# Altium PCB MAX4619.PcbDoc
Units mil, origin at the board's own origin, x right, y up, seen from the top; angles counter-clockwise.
Board outline 2750 x 2500 mil, 2 copper layers (Top, Bottom), stack 62 mil thick; 43 components, 17 nets, 117 pads, 7 vias.
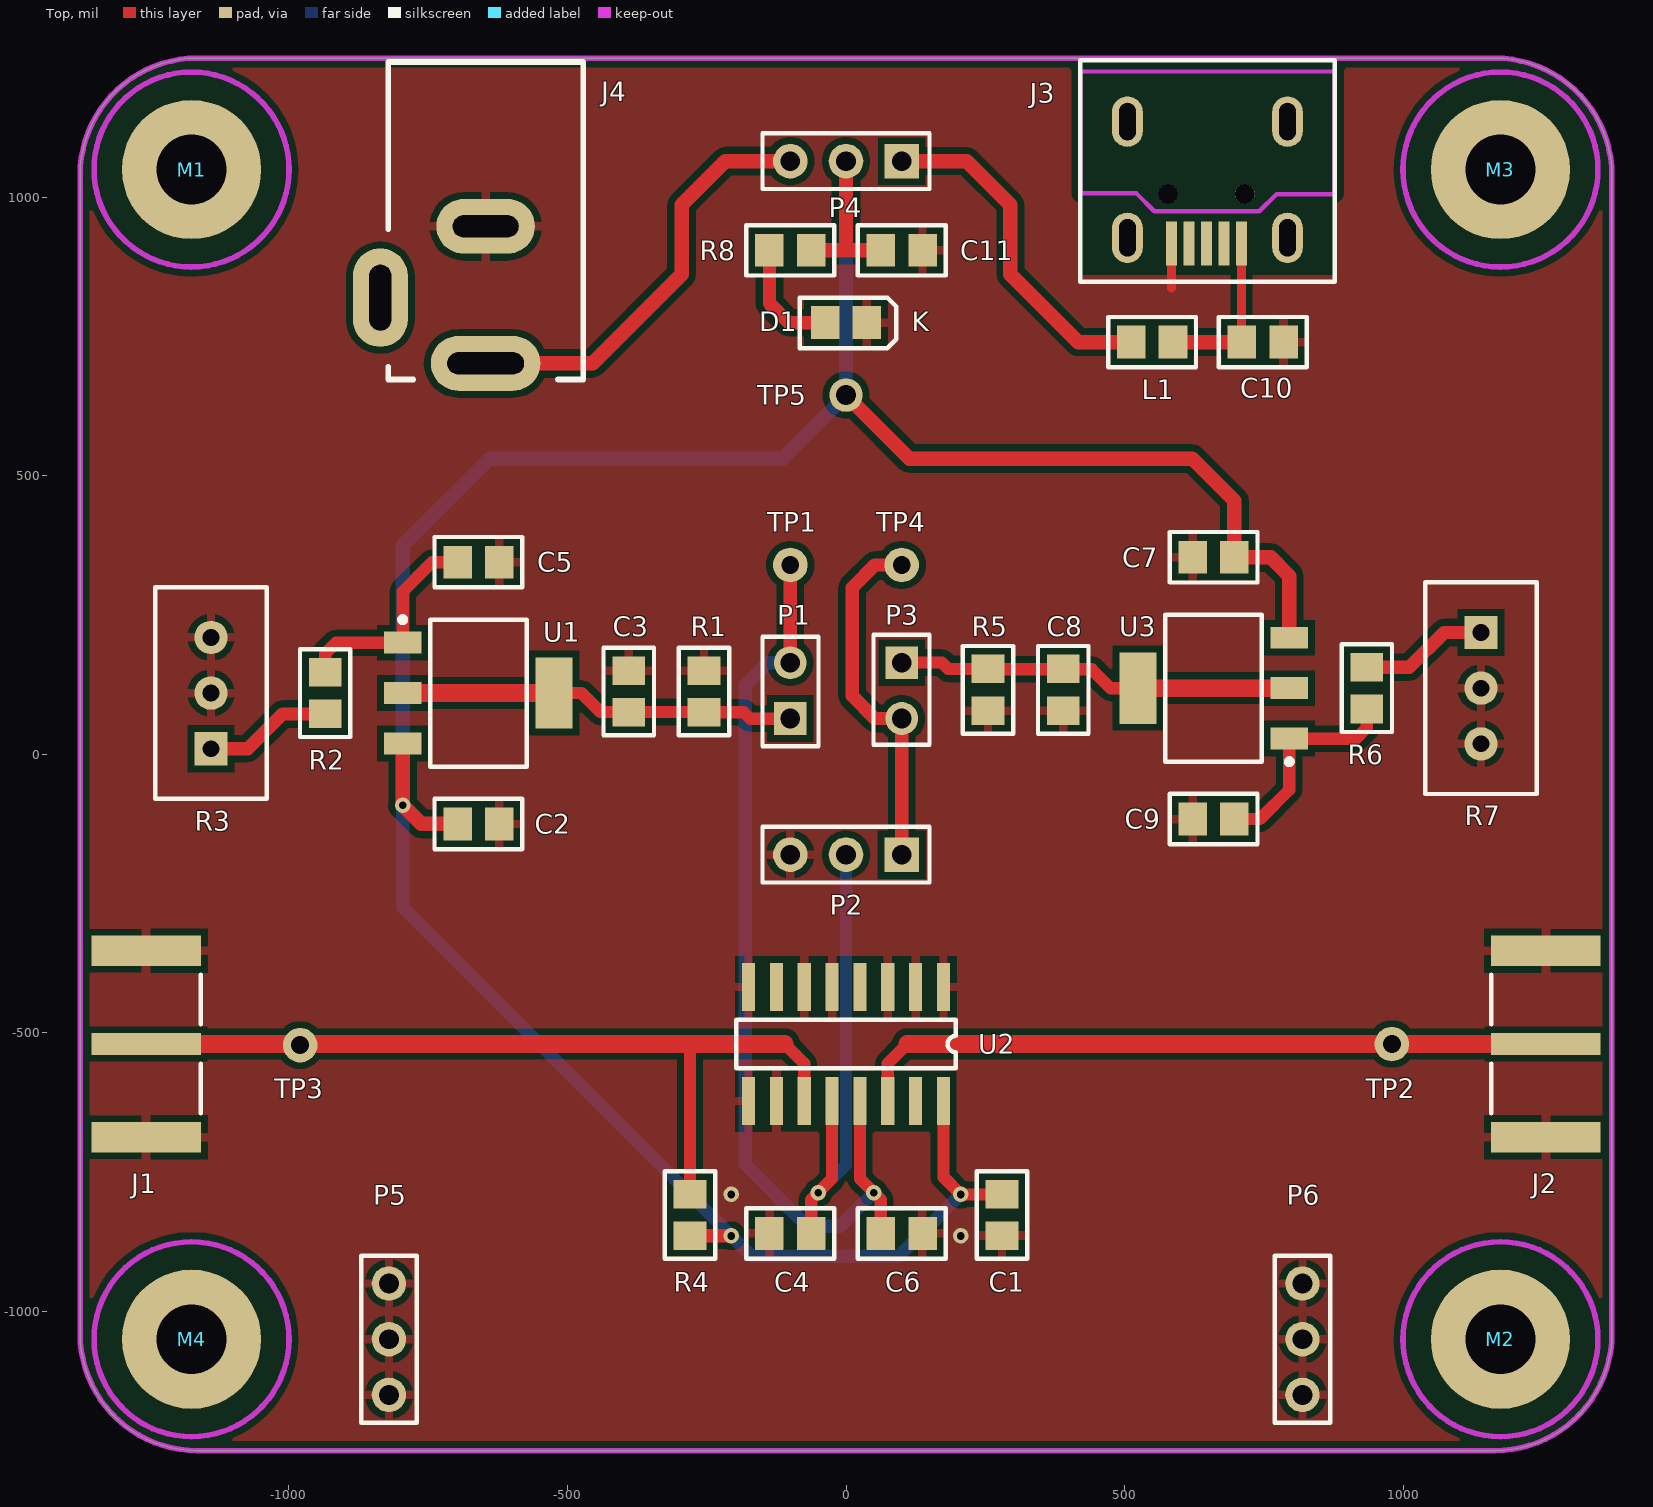
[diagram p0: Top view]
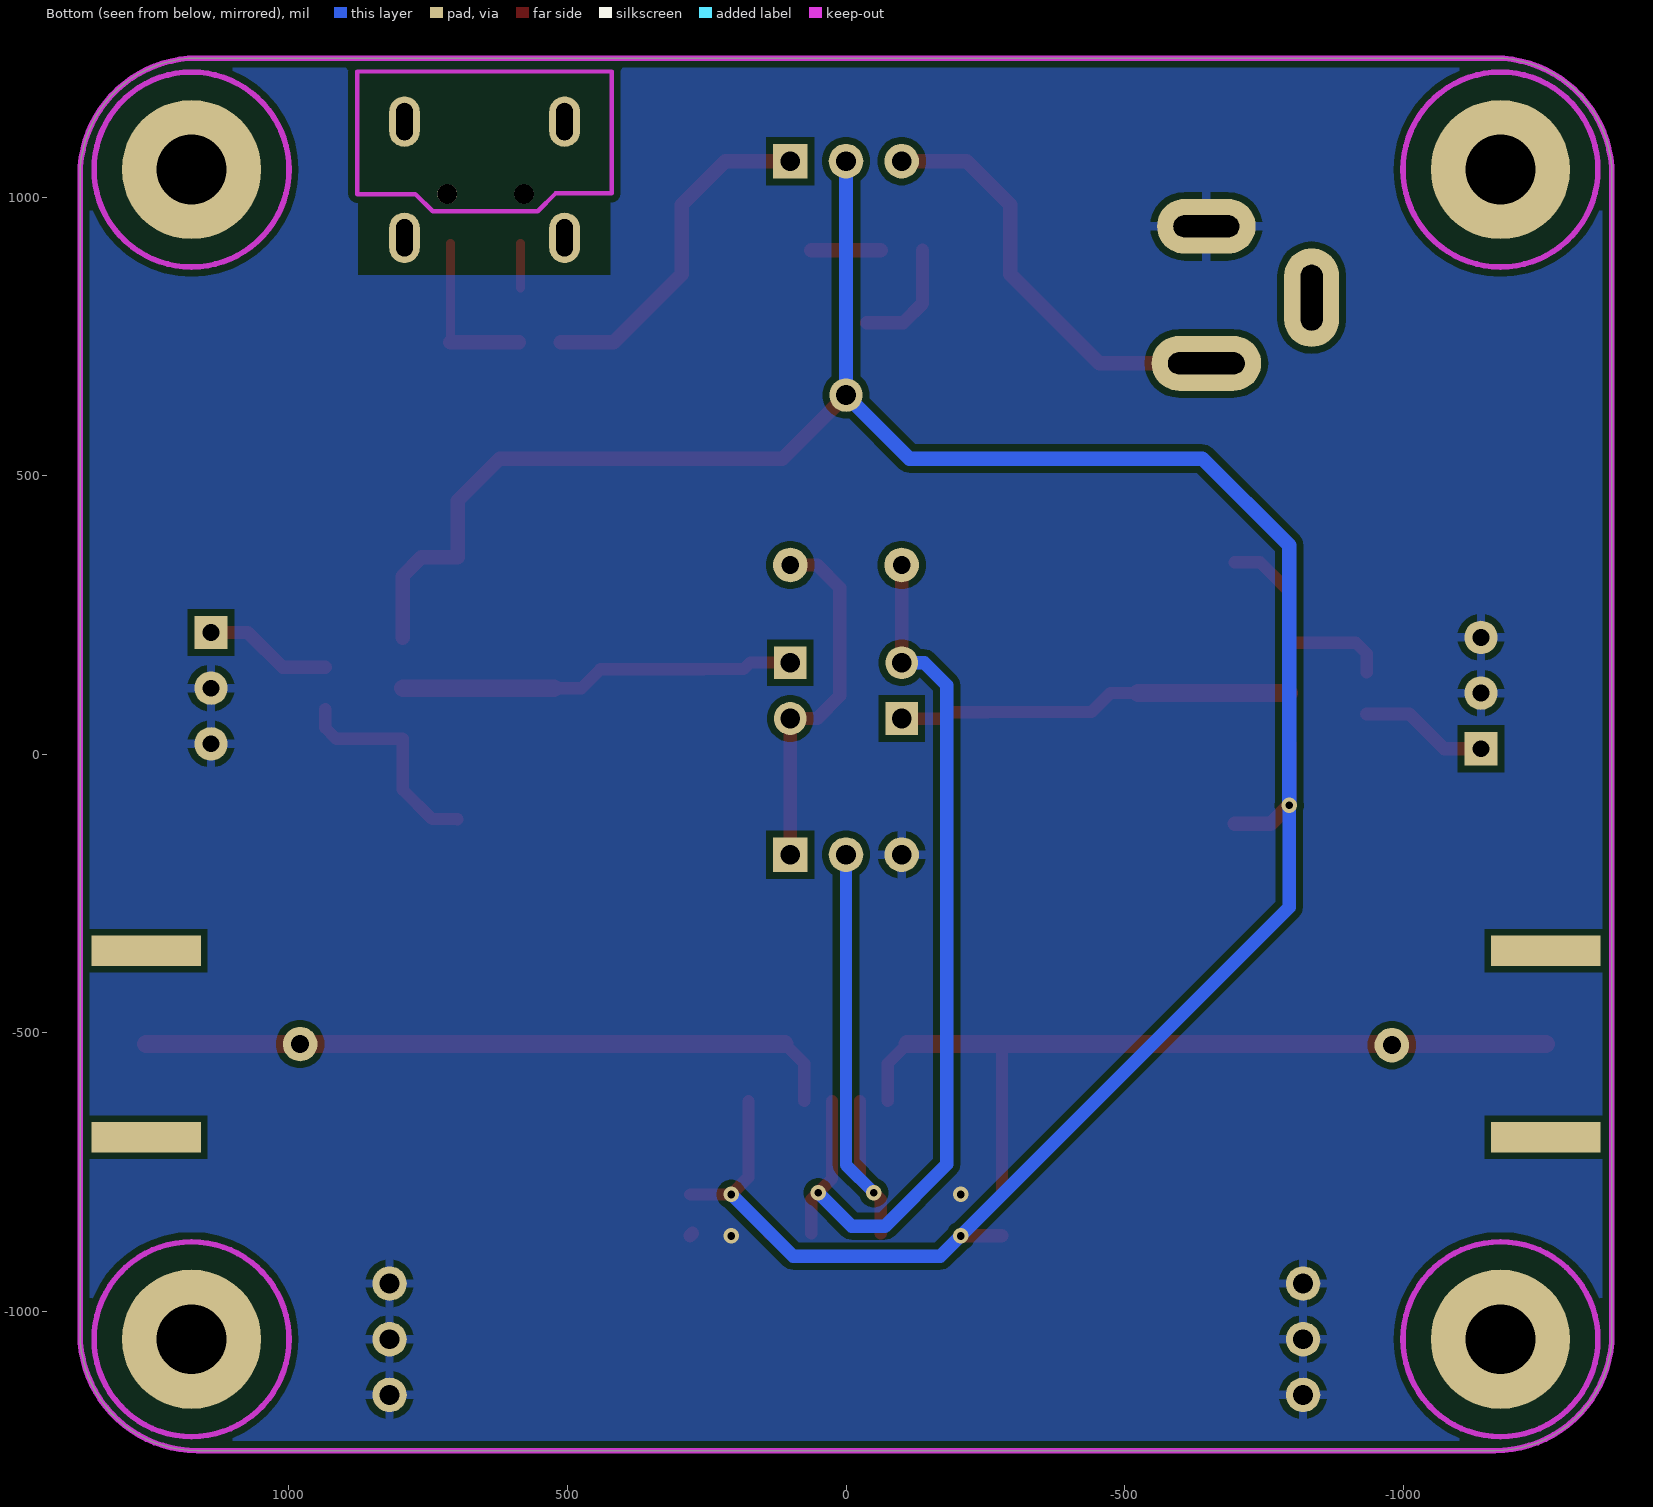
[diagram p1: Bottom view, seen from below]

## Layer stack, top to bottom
Top Solder: solder mask 0.4, Solder Resist, Dk 3.5
Top: signal copper 1.4
Dielectric1: core 59.2, FR-4, Dk 4.8
Bottom: signal copper 1.4
Bottom Solder: solder mask 0.4, Solder Resist, Dk 3.5

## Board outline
-1375,-1040 -1375,1040 cw(c-1165,1040) -1165,1250 1165,1250 cw(c1165,1040) 1375,1040 1375,-1040 cw(c1165,-1040) 1165,-1250 -1165,-1250 cw(c-1165,-1040)

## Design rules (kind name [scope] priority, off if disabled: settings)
Clearance Clearance_1 [InPolygon] p1: gap=12 ignorepadtopadclearanceinfootprint=FALSE except(0: Arc-Hole Track-Hole SMDPad-Hole THPad-Hole Via-Hole Fill-Hole Poly-Hole Region-Hole Text-Hole)
Clearance [All] p2: gap=9 ignorepadtopadclearanceinfootprint=FALSE except(0: Arc-Hole Track-Hole SMDPad-Hole THPad-Hole Via-Hole Fill-Hole Poly-Hole Region-Hole Text-Hole)
ComponentClearance [All] p1 off: gap=0 collisioncheckmode=3 verticalgap=10 showdistances=FALSE
FabricationTestPointUsage TestPointUsage [All] p1: valid=0 allowmultiple=FALSE
FabricationTestpoint Testpoint [All] p1: side=3 testpointundercomponent=TRUE minsize=40 maxsize=100 preferedsize=60 minholesize=0 maxholesize=40 preferedholesize=32 testpointgrid=1 allowsidetop=TRUE allowsidebottom=TRUE usegrid=TRUE gridtolerance=0.01
HoleSize [All] p1: absolutevalues=TRUE maxlimit=250 minlimit=10 maxpercent=80.000 minpercent=20.000
MinimumAnnularRing [All] p1: minimumring=7
PlaneClearance [All] p1: clearance=12
PlaneConnect [All] p1: planeconnectstyle=Relief reliefexpansion=12 reliefentries=4 reliefconductorwidth=12 reliefairgap=12
PolygonConnect [IsVia] p1: connectstyle=Direct reliefconductorwidth=10 reliefentries=4 polygonreliefangle="90 Angle" airgapwidth=10
PolygonConnect PolygonConnect_1 [All] p2: connectstyle=Relief reliefconductorwidth=16 reliefentries=4 polygonreliefangle="90 Angle" airgapwidth=12
RoutingVias [All] p1: holewidth=14 width=28 viastyle="Through Hole" minholewidth=14 minwidth=28 maxholewidth=14 maxwidth=28
SilkToSolderMaskClearance SilkscreenOverComponentPads [IsPad] p1: minsilkscreentomaskgap=10 clearancetoexposedcopper=TRUE
SolderMaskExpansion SolderMaskExpansion_1 [(IsVia)] p1: expansion=-14 istentingtop=FALSE
SolderMaskExpansion [All] p2: expansion=4 istentingtop=FALSE
Width [All] p1: maxlimit=32 minlimit=10 preferedwidth=12
23 further rules are at their usual default settings.

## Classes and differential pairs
component class MAX4619: C1 C2 C3 C4 C5 C6 C7 C8 C9 C10 C11 D1 J1 J2 J3 J4 L1 P1 P2 P3 P4 P5 P6 R1 R2 R3 R4 R5 R6 R7 R8 TP1 TP2 TP3 TP4 TP5 U1 U2 U3

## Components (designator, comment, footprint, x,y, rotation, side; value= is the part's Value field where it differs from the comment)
C1 "Cap" CC2012-0805 280,-827 r90 top value=0.1uF
C2 "Cap" CC2012-0805 -660,-125 r180 top value=1uF
C3 "Cap" CC2012-0805 -390,112.95 r270 top value=2.2uF
C4 "Cap" CC2012-0805 -100,-860 r0 top value=0.1uF
C5 "Cap" CC2012-0805 -660,345 r180 top value=0.1uF
C6 "Cap" CC2012-0805 100,-860 r180 top value=0.1uF
C7 "Cap" CC2012-0805 660,353.86 r0 top value=1uF
C8 "Cap" CC2012-0805 390,115.91 r90 top value=2.2uF
C9 "Cap" CC2012-0805 660,-116.14 r0 top value=0.1uF
C10 "Cap" CC2012-0805 748.27,740 r180 top value=0.01uF
C11 "Cap" CC2012-0805 100,905 r180 top value=0.1uF
D1 "LED" "CC2012-0805 LED" 0,775 r0 top
J1 "32K145-400L5" ROS-32K145-400L5_V -1355,-520 r90 top locked
J2 "32K145-400L5" ROS-32K145-400L5_V 1355,-520 r270 top locked
J3 "UX60-MB-5S8" "HRS UX60-MB-5S8 MINI-USB" 505.27,1136 r270 top locked
J4 "PJ-202A" PJ-202A-SLOTS -647,948 r180 top
L1 "Inductor" CC2012-0805 549.67,740 r180 top value=220R@100MHz
M1 "Comment" MOUNTING-HOLE-4-40 -1175,1050 r0 top locked
M2 "Comment" MOUNTING-HOLE-4-40 1175,-1050 r0 top locked
M3 "Comment" MOUNTING-HOLE-4-40 1175,1050 r0 top locked
M4 "Comment" MOUNTING-HOLE-4-40 -1175,-1050 r0 top locked
P1 "Header 2" HEADER2 -100,64.43 r0 top
P2 "Header 3" HEADER3#1 100,-180 r180 top
P3 "Header 2" HEADER2 100,164.43 r180 top
P4 "Header 3" HEADER3#1 100,1065 r180 top
P5 "Header 3" HEADER3#2 -820.5,-950 r270 top
P6 "Header 3" HEADER3#2 819.5,-950 r270 top
R1 "Res1" CC2012-0805 -255,112.95 r90 top value=DNP
R2 "Res1" CC2012-0805 -935,110 r270 top value="0 ohm"
R3 "500k" BOURNS-3296 -1140,110 r90 top
R4 "Res1" CC2012-0805 -280,-827 r90 top value=10k
R5 "Res1" CC2012-0805 255,115.91 r270 top value=DNP
R6 "Res1" CC2012-0805 935,118.86 r90 top value="0 ohm"
R7 "500k" BOURNS-3296 1140,118.86 r270 top
R8 "Res1" CC2012-0805 -100,905 r180 top value=10k
TP1 "TESTPOINT" TESTPOINT#1 -110,380 r90 top
TP2 "TESTPOINT" TESTPOINT#2 980,-520 r90 top
TP3 "TESTPOINT" TESTPOINT#2 -980,-522 r90 top
TP4 "TESTPOINT" TESTPOINT#3 110,-151.14 r270 top
TP5 "TESTPOINT" TESTPOINT#4 0,645 r90 top
U1 "LT3082IST#TRPBF" LT-ST-3-SOT-223_M -660,110 r0 top
U2 "MAX4619CSE+" SO-G16 0,-520 r180 top locked
U3 "LT3082IST#TRPBF" LT-ST-3-SOT-223_M 660,118.86 r180 top

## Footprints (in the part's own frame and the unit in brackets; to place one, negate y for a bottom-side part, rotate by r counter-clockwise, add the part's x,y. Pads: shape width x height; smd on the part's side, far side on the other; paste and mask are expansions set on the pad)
BOURNS-3296 [mil]
  rect 60x60 hole 30: CCW(-100,0)
  round 60 hole 30: CW(100,0) W(0,0)
  silkscreen extent -190,-100 190,100
CC2012-0805 [mm]
  rect 1.3x1.5 smd: 1(-0.95,0) 2(0.95,0)
  silkscreen extent -2,-1.15 2,1.15
"CC2012-0805 LED" [mm]
  rect 1.3x1.5 smd: 1(-0.95,0) 2(0.95,0)
  silkscreen extent -2.12,-1.16 2.3,1.14
HEADER2 [mm]
  rect 1.5x1.5 hole 0.9: 1(0,0)
  round 1.5 hole 0.9: 2(0,2.54)
  silkscreen extent -1.27,-1.27 1.29,3.73
HEADER3#1 [mil]
  rect 62x62 hole 35.43: 1(0,0)
  round 62 hole 35.43: 2(100,0) 3(200,0)
  silkscreen extent -50,-50 250,50
HEADER3#2 [mil]
  round 62 hole 35.43: 1(0,0) 2(100,0) 3(200,0)
  silkscreen extent -50,-50 250,50
"HRS UX60-MB-5S8 MINI-USB" [mm]
  oval 2.3x1.4 hole 0.762 slot 1.7 at 0 deg: 0(0,7.3) 0(0,0) 0(5.3,7.3) 0(5.3,0)
  round 0.9 hole 0.9 unplated: 0(3.3,5.35) 0(3.3,1.85)
  rect 2x0.5 smd: 1(5.55,5.2) 2(5.55,4.4) 3(5.55,3.6) 4(5.55,2.8) 5(5.55,2)
  Keep-Out Layer lines w0.203: 3.277,-2.145 -2.286,-2.145 -2.286,9.462 3.302,9.462 3.302,6.804 4.089,6.017 4.089,5.348 4.089,1.842 4.089,1.226 3.277,0.413 3.277,-2.145
  silkscreen extent -2.8,-2.15 7.3,9.45
LT-ST-3-SOT-223_M [mm] "SOT223, 4-Leads, Body 6.505x3.505mm, Pitch 2.3mm, IPC Low Density"
  rect 1.7x1 smd: 1(-3.45,2.3) 2(-3.45,0) 3(-3.45,-2.3)
  rect 1.7x3.25 smd: 4(3.45,0)
  silkscreen extent -3.57,-3.35 2.2,3.47, body extent -1.86,-3.35 1.86,3.35, height 1.8
MOUNTING-HOLE-4-40 [mil] "Mounting Hole w/ Annular Ring US #4-40/Metric M3"
  round 250 hole 125: 0(0,0)
  Keep-Out Layer circle w10: c0,0 r175
PJ-202A-SLOTS [mm]
  oval 5x2.5 hole 1 slot 3.5 at 0 deg mask+0.075: 1(0,6.248)
  oval 4.5x2.5 hole 1 slot 3 at 0 deg mask+0.075: 2(0,0)
  oval 2.5x4.5 hole 1 slot 3 at 90 deg mask+0.075: 3(4.801,3.251)
  silkscreen extent -4.45,-7.49 4.45,6.98
ROS-32K145-400L5_V [mm] "SMA Right Angle Jack, Edge Mount, 14.25x9.5x4.46mm, Rosenberger Recommended"
  rect 1x5 smd: 1(0,-2.5)
  rect 1.4x5 smd: MP(-4.25,-2.5) MP(4.25,-2.5)
  rect 1.4x5 smd far side paste-2: ""(-4.25,-2.5) ""(4.25,-2.5)
  silkscreen extent -3.15,-5 3.15,-5, body extent -4.75,-4.75 4.75,9.5, height 4.46
SO-G16 [mm]
  rect 0.6x2.2 smd: 1(-4.445,-2.6) 2(-3.175,-2.6) 3(-1.905,-2.6) 4(-0.635,-2.6) 5(0.635,-2.6) 6(1.905,-2.6) 7(3.175,-2.6) 8(4.445,-2.6) 9(4.445,2.6) 10(3.175,2.6) 11(1.905,2.6) 12(0.635,2.6) 13(-0.635,2.6) 14(-1.905,2.6) 15(-3.175,2.6) 16(-4.445,2.6)
  silkscreen extent -5,-1.1 5,1.1
TESTPOINT#1 [mil]
  round 62 hole 32: 1(-40,-10)
TESTPOINT#2 [mil]
  round 62 hole 32: 1(0,0)
TESTPOINT#3 [mil]
  round 62 hole 32: 1(-491.14,-10)
TESTPOINT#4 [mil]
  round 60 hole 35.43: 1(0,0)

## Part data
C1 C2 C3 C4 C5 C6 C7 C8 C9 C11: "C0805C105K4RACTU"
C10: "Capacitor"
D1: library part LED0, "Typical LED"
J1 J2: "SMA Right Angle Jack, Edge Mount, Up to 18 GHz, -55 to 155 degC"
J3: library part "Header 5", "Header, 5-Pin"
J4: library part "PWR JACK DC (PJ-202A)", "Low Voltage Power Supply Connector"
L1: "MPZ2012S221A"
P1 P3: "Header, 2-Pin"
P2 P4 P5 P6: "Header, 3-Pin"
R1 R2 R4 R5 R6 R8: "Resistor"
R3 R7: library part "RPot SM", "Square Trimming Potentiometer"
U1 U3: "200 mA Single Resistor Low Dropout Linear Regulator, 1.2 to 40 V Vin, Adjustable Vout, 3-pin SOT223 (ST-3), -40 to 125 degC, Pb-Free, Tape and Reel", Dropout Voltage(V)=1.3, Manufacturer="Linear Technology", Output Voltage=Adj, Supplier Part Number 1=LT3082IST#TRPBF-ND
U2: library part MAX4619

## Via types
v1: diameter 28, hole 14, Top to Bottom, 7 vias

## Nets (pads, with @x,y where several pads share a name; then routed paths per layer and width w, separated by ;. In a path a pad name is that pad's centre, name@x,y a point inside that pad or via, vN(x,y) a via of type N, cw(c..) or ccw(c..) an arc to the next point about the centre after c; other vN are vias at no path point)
GND: C1.1 C2.1 C3.1 C4.1 C5.1 C6.1 C7.1 C8.1 C9.1 C10.1 C11.1 D1.2 J1.MP J2.MP J3.5 J4.2 P2.3 P5.1 P5.2 P5.3 P6.1 P6.2 P6.3 R1.2 R3.CW R3.W R5.2 R7.CW R7.W U2.1 U2.2 U2.3 U2.5 U2.6 U2.8 U2.9 U2.10 | length 86.7
  Top w16: 584.01,837.01 J3.5
  Top w24: C1.1@275.6,-860 C1.1
  other v1: 206,-864.4 -206,-790
NetC3_2: C3.2 P1.1 R1.1 U1.2 U1.4 | length 715.1
  Top w22: U1.4 -475,110 -441,76 -255.45,76 R1.1 -183.55,75.55 -172,64 -100.43,64 P1.1
  Top w32: U1.2 U1.4
NetC4_2: C4.2 P2.2 U2.12 | length 880.9
  Top w22: C4.2 -62.6,-799.6 v1(-50,-787) -25,-762 U2.12
  Bottom w22: v1(-50,-787) 0,-737 P2.2
NetC5_2: C5.2 R2.1 U1.1 | length 392.8
  Top w22: R2.1 -935,181 -915.45,200.55 U1.1 -795.83,292.17 -743.1,344.9 -697.51,344.9 C5.2
NetC8_2: C8.2 P3.1 R5.1 U3.2 U3.4 | length 714.4
  Top w22: P3.1 100.43,164.86 172,164.86 183.55,153.31 R5.1 ; R5.1@255.45,152.86 441,152.86 475,118.86 U3.4
  Top w32: U3.4 U3.2
NetC9_2: C9.2 R6.1 U3.1 | length 392.9
  Top w22: C9.2@697.3,-116.25 C9.2 743,-116.14 795.72,-63.42 795.72,28.2 915.34,28.2 935,47.86 R6.1
NetD1_1: D1.1 R8.2 | length 209.8
  Top w24: R8.2 -137.4,809.4 -103,775 D1.1
NetJ1_1: J1.1 R4.2 TP3.1 U2.11 | length 1531
  Top w22: R4.2 -280,-522 ; -110,-520 -75,-555 U2.11
  Top w32: J1.1 -280,-520 -110,-520
NetJ2_1: J2.1 TP2.1 U2.14 | length 1263.4
  Top w22: U2.14 75,-555 110,-520
  Top w32: 110,-520 J2.1
NetJ4_1: J4.1 P4.3 | length 770.6
  Top w26: J4.1 -455,702 -295,862 -295,987 -217,1065 P4.3
NetL1_2: L1.2 P4.1 | length 620.1
  Top w26: P4.1 217,1065 295,987 295,862 417,740 L1.2
NetR2_2: R2.2 R3.CCW | length 230.9
  Top w24: R3.CCW -1074,10 -1011.4,72.6 R2.2
NetR6_2: R6.2 R7.CCW | length 230.9
  Top w24: R6.2 1011.4,156.26 1074,218.86 R7.CCW
VGLITCH: P2.1 P3.2 TP4.1 | length 650.5
  Top w24: P2.1 P3.2 51.57,64.43 11,105 11,299.43 51.57,340 TP4.1
VIN: C1.2 C2.2 C7.2 C11.2 P4.2 R4.1 R8.1 TP5.1 U1.3 U2.16 U3.3 | length 5219.5
  Top w22: U2.16 175,-759 v1(206,-790) C1.2@279.6,-790
  Top w24: R4.1 v1(-206,-864.4)
  Top w26: U1.3 v1(-795.83,-91.32) -762.25,-124.9 C2.2@-697.51,-124.9 ; R8.1 C11.2 ; TP5.1 114,531 622,531 697.4,455.6 C7.2 ; 0,907 P4.2 ; C7.2@697.51,353.75 762.25,353.75 795.83,320.17 U3.3
  Bottom w24: v1(-795.83,-91.32) -795.83,-274.58 v1(-206,-864.4) -169.4,-901 95,-901 v1(206,-790)
  Bottom w26: v1(-795.83,-91.32) -795.83,375.17 -640,531 -114,531 TP5.1 P4.2
VNORMAL: C6.2 P1.2 TP1.1 U2.13 | length 1688.4
  Top w22: U2.13 25,-762 62.6,-799.6 C6.2
  Top w24: P1.2 TP1.1
  Bottom w24: P1.2 -140.57,164.43 -181,124 -181,-736 -70,-847 -10,-847 v1(50,-787)
VUSB: C10.2 J3.1 L1.1 | length 298.4
  Top w16: C10.2@709.99,742.87 J3.1
  Top w26: L1.1 C10.2
pads on no net: J1. J2. J3.0 J3.2 J3.3 J3.4 J4.3 M1.0 M2.0 M3.0 M4.0 U2.4 U2.7 U2.15

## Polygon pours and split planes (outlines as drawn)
GND on Bottom "GND_L02_P001" (solid, remove dead copper, pour order 1): -1375,1250 1375,1250 1375,-1250 -1375,-1250
GND on Top "GND_L01_P000" (solid, remove dead copper, pour order 0): -1375,1250 1375,1250 1375,-1250 -1375,-1250

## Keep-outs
Keep-Out Layer:
  the board outline again, w10

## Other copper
Top:
  pour cut-out: 877,860.08 877,999.08 421.72,999.08 422,998.8 422,860.08
Bottom:
  pour cut-out: 877,860.08 877,999.08 421.72,999.08 422,998.8 422,860.08

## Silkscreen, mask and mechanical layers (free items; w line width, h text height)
Top Overlay:
  text "K" at 118,760 h35
Silkscreen Top:
  text "V_Input Select" at -230,1158 h35
  text "Jack" at -308,1048 h35
  text "USB" at 182,1048 h35
  text "2.0 to 5.5V" at -838,557 h35
  text "V_Input" at -108,541 h35
  text "5V Nominal" at -820.51,487 h35
  text "V_Normal Adjust" at -1313,362 h35 r270
  text "V_Normal" at -440,322 h35
  text "V_Glitch" at 183,322 h35
  text "Enable" at 16,17 h35 r90
  text "Glitch Select" at -206,-96 h35
  text "V_Glitch Adjust" at 1313,-126 h35 r90
  text "GND" at -274,-197 h35
  text "V_Glitch" at 183,-197 h35
  text "Glitch In" at -901,-502 h35
  text "Glitch Out" at 598,-535 h35
  text "(Crowbar)" at -903.92,-572 h35
  text "GND" at -867,-865 h35
  text "GND" at 773,-865 h35
  text "MAX4619 Fault Injection Adapter" at -590,-1124 h90
Silkscreen Bottom:
  text "Joe Grand (@joegrand)" at 351.5,-1056 h35
  text "Lennert Wouters (@lennertwo)" at 462.3,-1138 h35
Board Shape:
  the board outline again, w10
Drill Drawing:
  drawing of 1722 lines, arcs and shapes, not listed
  text "FABRICATION / ASSEMBLY NOTES:" at -2169.83,4713 h59.06
  text "(UNLESS OTHERWISE SPECIFIED)" at -2169.83,4613 h59.06
  text "1. MATERIAL: EPOXY GLASS LAMINATE FR-4" at -2169.83,4413 h59.06
  text "FINISHED COPPER WEIGHT SHALL BE 1 OZ ON ALL LAYERS" at -2069.83,4313 h59.06
  text "2. NUMBER OF ELECTRICAL LAYERS: 2" at -2169.83,4113 h59.06
  text "3. THICKNESS: 0.062\" (FINISHED)" at -2165.83,3913 h59.06
  text "4. FINISH: IMMERSION PLATE EXPOSED AREAS AFTER APPLYING SOLDER MASK WITH ELECTROLESS NICKEL IMMERSION GOLD" at -2164,3705 h59.06
  text "5. SOLDER MASK: LIQUID PHOTOIMAGEABLE SOLDER MASK PER IPC-SM-840" at -2164,3505 h59.06
  text "COLOR ANY, 10/ 50um THK, BOTH SIDES, AFTER PLATING. REGISTRATION TO BE WITHIN +/- 50um" at -2049,3405 h59.06
  text "OF THE ASSOCIATED CIRCUIT LAYER." at -2049,3305 h59.06
  text "6. SILKSCREEN: SILKSCREEN BOTH SIDES USING WHITE NONCONDUCTIVE INK." at -2164,3105 h59.06
  text "7. BARE BOARD ELECTRICAL TEST: 100% SCHEMATIC NETLIST TEST COVERAGE REQUIRED." at -2164,2905 h59.06
  text "8. RoHS: PARTS SHALL BE RoHS COMPLIANT PER EUROPEAN UNION DIRECTIVE 2002/95/EC." at -2164,2705 h59.06
  text "9. THE BOARD MUST BE LEAD-FREE ASSEMBLY PROCESS COMPATIBLE AND BE ABLE TO HANDLE A MINIMUM" at -2164,2505 h59.06
  text "OF 5 CYCLES AT 260 DEGREES CELSIUS" at -2041,2405 h59.06
  text "10. NO QA/QC/TEST/FAB MARKINGS ANYWHERE ON THE PCB" at -2164,2205 h59.06
  text ".PCB_FILE_NAME_NO_PATH" at -2280.7,-2105.88 h70
  text "COMPANY:" at -452.29,-2331.75 h39.37
  text "Grand Idea Studio, Inc." at -316.25,-2460 h49.21
  text "TITLE:" at -452.29,-2646.71 h39.37
  text "MAX4619 Fault Injection Adapter" at -316.25,-2771 h49.21
  text "DRAWN:" at -452.29,-2961.67 h39.37
  text "Joe Grand" at -316.25,-3083 h49.21
  text "DESIGN FILES DISTRIBUTED UNDER A" at -2167.08,-3089.39 h34.45
  text "CREATIVE COMMONS ATTRIBUTION 4.0 INTERNATIONAL LICENSE" at -2167.08,-3168.13 h34.45
  text "2023 cc by 4.0" at -2171.33,-3251.28 h34.45
  text "ISSUE:" at -452.29,-3276.63 h39.37
  text "DATE:" at 20.16,-3276.63 h39.37
  text ".PRINT_DATE" at 316.3,-3298.88 h49.21
  text "A" at -182.7,-3304.88 h49.21
  text ".LEGEND" at 1280,-3344 h60

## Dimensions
1165,1250 to 1165,-1250 on Drill Drawing
-1375,1040 to 1375,1047 on Drill Drawing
